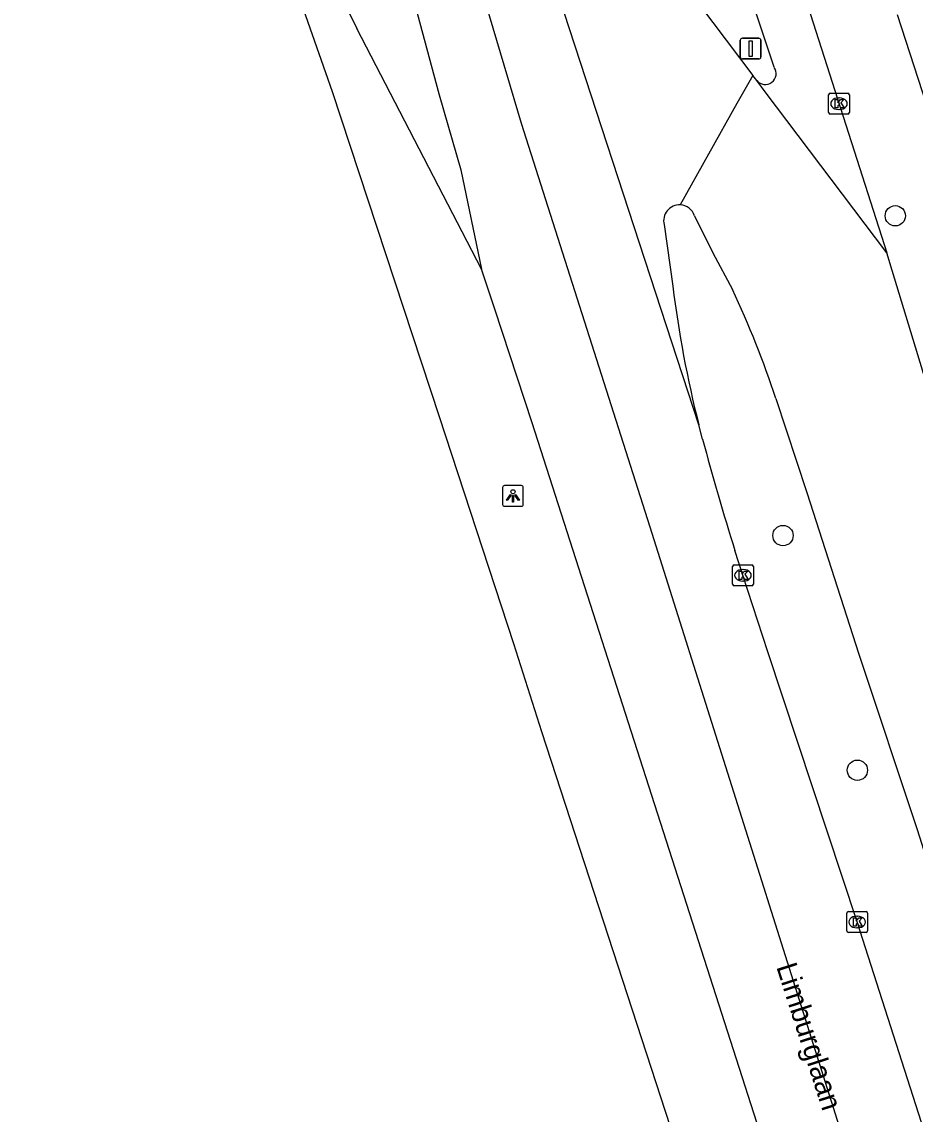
# Model space of a CAD drawing. Extents: x 159503 to 160347, y 382525 to 383272.
# Drawn here: x 159508.4 to 159551.5, y 382877.9 to 382930.5 of the extents above; entities that cross this region are included whole.
import ezdxf

# ---------------------------------------------------------------- set-up
doc = ezdxf.new("R2010")
doc.units = 0
for name, color, linetype in [('IMGEO_Boom', 7, 'Continuous'), ('IMGEO_Fietspad_open', 7, 'Continuous'), ('IMGEO_Kolk', 7, 'Continuous'), ('IMGEO_Lichtpunt', 7, 'Continuous'), ('IMGEO_Openbare_ruimte_label', 7, 'Continuous'), ('IMGEO_Pand', 7, 'Continuous'), ('IMGEO_Rijbaan_lokaal_open', 7, 'Continuous'), ('IMGEO_Rijbaan_regionaal_gesloten', 7, 'Continuous'), ('IMGEO_Verkeersbordpaal', 7, 'Continuous')]:
    doc.layers.add(name, color=color, linetype=linetype)

msp = doc.modelspace()

# ---------------------------------------------------------------- linework, layer by layer
at = {"layer": 'IMGEO_Boom'}
for centre in [(159550.494, 382921.204), (159545.083, 382905.796), (159548.666, 382894.489)]:
    msp.add_circle(centre, 0.489, dxfattribs=at)
at = {"layer": 'IMGEO_Fietspad_open'}
for points in [[(159532.054, 382976.364), (159532.765, 382973.478), (159533.952, 382969.832), (159535.582, 382964.78), (159537.218, 382959.569), (159538.641, 382955.193), (159547.321, 382928.042), (159550.079, 382919.415)], [(159544.665, 382928.357), (159540.08, 382942.127), (159539.891, 382942.783), (159538.071, 382948.551), (159535.904, 382955.29), (159529.596, 382975.094)]]:
    msp.add_lwpolyline(points, dxfattribs=at)
msp.add_arc((159544.223, 382928.062), 0.531, 220.3653, 33.6985, dxfattribs=at)
at = {"layer": 'IMGEO_Kolk'}
for p, q in [((159547.281, 382926.179), (159547.281, 382927.031)), ((159547.356, 382927.105), (159548.208, 382927.105)), ((159547.769, 382926.885), (159547.794, 382926.885)), ((159548.282, 382927.031), (159548.282, 382926.179)), ((159547.792, 382926.325), (159547.767, 382926.325)), ((159548.208, 382926.105), (159547.356, 382926.105)), ((159542.654, 382903.456), (159542.654, 382904.308)), ((159542.729, 382904.382), (159543.581, 382904.382)), ((159543.655, 382904.308), (159543.655, 382903.456)), ((159543.142, 382904.162), (159543.167, 382904.162)), ((159543.581, 382903.382), (159542.729, 382903.382)), ((159543.165, 382903.602), (159543.14, 382903.602)), ((159548.158, 382886.752), (159548.158, 382887.604)), ((159548.233, 382887.678), (159549.085, 382887.678)), ((159548.646, 382887.458), (159548.671, 382887.458)), ((159549.159, 382887.604), (159549.159, 382886.752)), ((159548.669, 382886.898), (159548.644, 382886.898)), ((159549.085, 382886.678), (159548.233, 382886.678))]:
    msp.add_line(p, q, dxfattribs=at)
for points in [[(159547.281, 382926.179), (159547.281, 382927.031)], [(159547.356, 382927.105), (159548.208, 382927.105)], [(159548.282, 382927.031), (159548.282, 382926.179)], [(159547.602, 382926.805), (159547.725, 382926.805), (159547.725, 382926.654), (159547.855, 382926.805), (159548.019, 382926.805), (159547.873, 382926.654), (159548.026, 382926.405), (159547.874, 382926.405), (159547.789, 382926.569), (159547.725, 382926.502), (159547.725, 382926.405), (159547.602, 382926.405), (159547.602, 382926.805)], [(159548.208, 382926.105), (159547.356, 382926.105)], [(159542.654, 382903.456), (159542.654, 382904.308)], [(159542.729, 382904.382), (159543.581, 382904.382)], [(159543.655, 382904.308), (159543.655, 382903.456)], [(159542.975, 382904.082), (159543.098, 382904.082), (159543.098, 382903.931), (159543.228, 382904.082), (159543.392, 382904.082), (159543.246, 382903.931), (159543.399, 382903.682), (159543.247, 382903.682), (159543.162, 382903.846), (159543.098, 382903.779), (159543.098, 382903.682), (159542.975, 382903.682), (159542.975, 382904.082)], [(159543.581, 382903.382), (159542.729, 382903.382)], [(159548.158, 382886.752), (159548.158, 382887.604)], [(159548.233, 382887.678), (159549.085, 382887.678)], [(159548.479, 382887.378), (159548.602, 382887.378), (159548.602, 382887.227), (159548.732, 382887.378), (159548.896, 382887.378), (159548.75, 382887.227), (159548.903, 382886.978), (159548.751, 382886.978), (159548.666, 382887.142), (159548.602, 382887.075), (159548.602, 382886.978), (159548.479, 382886.978), (159548.479, 382887.378)], [(159549.159, 382887.604), (159549.159, 382886.752)], [(159549.085, 382886.678), (159548.233, 382886.678)]]:
    msp.add_lwpolyline(points, dxfattribs=at)
for centre, start, end in [((159547.358, 382927.029), 91.552, 178.448), ((159547.358, 382927.029), 91.552, 178.448), ((159548.206, 382927.029), 1.552, 88.448), ((159548.206, 382927.029), 1.552, 88.448), ((159547.358, 382926.181), 181.552, 268.448), ((159547.358, 382926.181), 181.552, 268.448), ((159548.206, 382926.181), 271.552, 358.448), ((159548.206, 382926.181), 271.552, 358.448), ((159542.731, 382904.306), 91.552, 178.448), ((159542.731, 382904.306), 91.552, 178.448), ((159543.579, 382904.306), 1.552, 88.448), ((159543.579, 382904.306), 1.552, 88.448), ((159542.731, 382903.458), 181.552, 268.448), ((159542.731, 382903.458), 181.552, 268.448), ((159543.579, 382903.458), 271.552, 358.448), ((159543.579, 382903.458), 271.552, 358.448), ((159548.235, 382887.602), 91.552, 178.448), ((159548.235, 382887.602), 91.552, 178.448), ((159549.083, 382887.602), 1.552, 88.448), ((159549.083, 382887.602), 1.552, 88.448), ((159548.235, 382886.754), 181.552, 268.448), ((159548.235, 382886.754), 181.552, 268.448), ((159549.083, 382886.754), 271.552, 358.448), ((159549.083, 382886.754), 271.552, 358.448)]:
    msp.add_arc(centre, 0.0765, start, end, dxfattribs=at)
for centre, major_axis, ratio, start_param, end_param in [((159547.768, 382926.605), (-0.387, 0.002), 0.722429, 4.712389, 7.853982), ((159547.793, 382926.605), (-0.39, 0.002), 0.717154, 1.570796, 4.712389), ((159543.141, 382903.882), (-0.387, 0.002), 0.722429, 4.712389, 7.853982), ((159543.166, 382903.882), (-0.39, 0.002), 0.717154, 1.570796, 4.712389), ((159548.645, 382887.178), (-0.387, 0.002), 0.722429, 4.712389, 7.853982), ((159548.67, 382887.178), (-0.39, 0.002), 0.717154, 1.570796, 4.712389)]:
    msp.add_ellipse(centre, major_axis=major_axis, ratio=ratio, start_param=start_param, end_param=end_param, dxfattribs=at)
at = {"layer": 'IMGEO_Lichtpunt'}
for p, q in [((159531.574, 382908.109), (159531.574, 382907.302)), ((159531.574, 382908.109), (159531.574, 382907.302)), ((159532.476, 382908.204), (159531.668, 382908.204)), ((159532.476, 382908.204), (159531.668, 382908.204)), ((159532.57, 382907.302), (159532.57, 382908.109)), ((159532.57, 382907.302), (159532.57, 382908.109)), ((159531.668, 382907.208), (159532.476, 382907.208)), ((159531.668, 382907.208), (159532.476, 382907.208))]:
    msp.add_line(p, q, dxfattribs=at)
for points in [[(159531.948, 382907.773), (159531.987, 382907.745), (159531.799, 382907.483), (159531.761, 382907.51), (159531.948, 382907.773)], [(159532.05, 382907.725), (159532.097, 382907.725), (159532.097, 382907.403), (159532.05, 382907.403), (159532.05, 382907.725)], [(159532.16, 382907.745), (159532.198, 382907.772), (159532.385, 382907.51), (159532.346, 382907.482), (159532.16, 382907.745)]]:
    msp.add_lwpolyline(points, dxfattribs=at)
msp.add_circle((159532.073, 382907.907), 0.0994, dxfattribs=at)
for centre, start, end in [((159531.668, 382908.109), 90, 180), ((159531.668, 382908.109), 90, 180), ((159532.476, 382908.109), 0, 90), ((159532.476, 382908.109), 0, 90), ((159531.668, 382907.302), 180, 270), ((159531.668, 382907.302), 180, 270), ((159532.476, 382907.302), 270, 0), ((159532.476, 382907.302), 270, 360)]:
    msp.add_arc(centre, 0.0946, start, end, dxfattribs=at)
at = {"layer": 'IMGEO_Pand'}
msp.add_lwpolyline([(159557.842, 382908.578), (159550.597, 382930.894)], dxfattribs=at)
at = {"layer": 'IMGEO_Rijbaan_lokaal_open'}
for points in [[(159543.818, 382927.718), (159543.632, 382927.965)], [(159550.079, 382919.415), (159544.222, 382927.182), (159543.818, 382927.718)], [(159540.824, 382921.208), (159541.709, 382919.418), (159542.645, 382917.647)], [(159553.797, 382907.263), (159553.741, 382907.489), (159553.201, 382909.181), (159550.348, 382918.574), (159550.079, 382919.415)], [(159544.733, 382912.397), (159546.225, 382907.873), (159548.742, 382900.089), (159551.541, 382891.638), (159559.371, 382866.945), (159560.95, 382861.963), (159569.974, 382833.753), (159580.757, 382800.012), (159586.93, 382780.584), (159588.663, 382775.19), (159596.758, 382750), (159598.169, 382745.608), (159601.26, 382736.112), (159606.876, 382718.49), (159612.558, 382700.837), (159620.67, 382675.522)]]:
    msp.add_lwpolyline(points, dxfattribs=at)
for centre, radius, start, end in [((159540.098, 382920.96), 0.767, 18.8831, 87.324), ((159503.006, 382898.842), 43.873, 17.9966, 25.3802)]:
    msp.add_arc(centre, radius, start, end, dxfattribs=at)
at = {"layer": 'IMGEO_Rijbaan_regionaal_gesloten'}
for points in [[(159525.731, 382973.831), (159526.262, 382971.839), (159531.911, 382951.211), (159534.655, 382941.092), (159535.756, 382938.861), (159537.052, 382936.737), (159538.443, 382934.847), (159543.632, 382927.965)], [(159541.027, 382911.134), (159532.466, 382937.365), (159522.84, 382972.833)], [(159519.416, 382971.652), (159520.539, 382967.272), (159525.031, 382950.924), (159528.903, 382937.675), (159532.465, 382925.666), (159538.661, 382906.219), (159549.889, 382870.657), (159551.83, 382864.602), (159554.195, 382857.243), (159556.524, 382849.66), (159558.952, 382842.239), (159561.272, 382834.784), (159563.72, 382827.229), (159566.168, 382819.674), (159568.54, 382812.355), (159570.89, 382804.901), (159573.171, 382797.667)], [(159516.385, 382970.606), (159518.445, 382963.205), (159519.993, 382957.642), (159522.063, 382950.206), (159524.211, 382942.487), (159526.36, 382934.768), (159527.46, 382930.967), (159528.522, 382927.035), (159529.563, 382923.424), (159530.549, 382918.632)], [(159508.406, 382967.961), (159509.421, 382965.565), (159510.503, 382962.771), (159512.147, 382958.547), (159514.37, 382952.835), (159523.362, 382927.199), (159528.519, 382911.541), (159532.099, 382900.604), (159533.454, 382896.362), (159544.464, 382862.528), (159544.527, 382862.333), (159555.534, 382828.133), (159564.967, 382798.597), (159574.371, 382769.067), (159580.527, 382750), (159582.772, 382743.045), (159593.058, 382710.177), (159601.476, 382683.957), (159610.06, 382658.166)], [(159530.549, 382918.632), (159524.546, 382930.23)], [(159543.632, 382927.965), (159542.866, 382926.616), (159540.134, 382921.726)], [(159539.353, 382920.777), (159539.777, 382917.806)], [(159607.414, 382678.502), (159600.947, 382698.584), (159588.32, 382737.927), (159584.455, 382750), (159577.507, 382771.704), (159568.662, 382799.479), (159565.633, 382809.239), (159558.739, 382830.76), (159548.31, 382863.508), (159546.781, 382868.311), (159533, 382911.233), (159531.19, 382916.706), (159530.549, 382918.632)], [(159541.207, 382910.445), (159541.027, 382911.134)], [(159616.35, 382674.798), (159612.315, 382687.423), (159602.362, 382719.194), (159592.595, 382750), (159589.136, 382760.908), (159577.422, 382797.414), (159561.837, 382846.103), (159555.533, 382865.751), (159548.656, 382887.185), (159544.346, 382900.196), (159543.155, 382903.882), (159542.768, 382905.078)]]:
    msp.add_lwpolyline(points, dxfattribs=at)
for centre, radius, start, end in [((159555.628, 382945.794), 34.761, 197.6547, 206.5997), ((159540.099, 382920.959), 0.768, 87.364, 193.7292), ((159592.472, 382924.225), 53.085, 186.9456, 194.2771), ((159666.705, 382944.036), 129.916, 194.98453, 197.44977)]:
    msp.add_arc(centre, radius, start, end, dxfattribs=at)
at = {"layer": 'IMGEO_Verkeersbordpaal'}
for p, q in [((159543.025, 382928.859), (159543.025, 382929.659)), ((159543.025, 382929.659), (159543.025, 382928.859)), ((159543.125, 382929.759), (159543.915, 382929.759)), ((159543.915, 382929.759), (159543.125, 382929.759)), ((159544.015, 382929.659), (159544.015, 382928.859)), ((159544.015, 382928.859), (159544.015, 382929.659)), ((159543.915, 382928.759), (159543.125, 382928.759)), ((159543.125, 382928.759), (159543.915, 382928.759))]:
    msp.add_line(p, q, dxfattribs=at)
msp.add_lwpolyline([(159543.445, 382929.634), (159543.595, 382929.634), (159543.595, 382928.884), (159543.445, 382928.884), (159543.445, 382929.634)], dxfattribs=at)
for centre, start, end in [((159543.125, 382929.659), 90, 180), ((159543.125, 382929.659), 90, 180), ((159543.915, 382929.659), 0, 90), ((159543.915, 382929.659), 360, 90), ((159543.125, 382928.859), 180, 270), ((159543.125, 382928.859), 180, 270), ((159543.915, 382928.859), 270, 0), ((159543.915, 382928.859), 270, 0)]:
    msp.add_arc(centre, 0.1, start, end, dxfattribs=at)

# ---------------------------------------------------------------- texts
at = {"layer": 'IMGEO_Openbare_ruimte_label'}
msp.add_text('Limburglaan', height=1, rotation=287.8189, dxfattribs=at).set_placement((159544.751, 382885.025))

doc.saveas('drawing.dxf')
